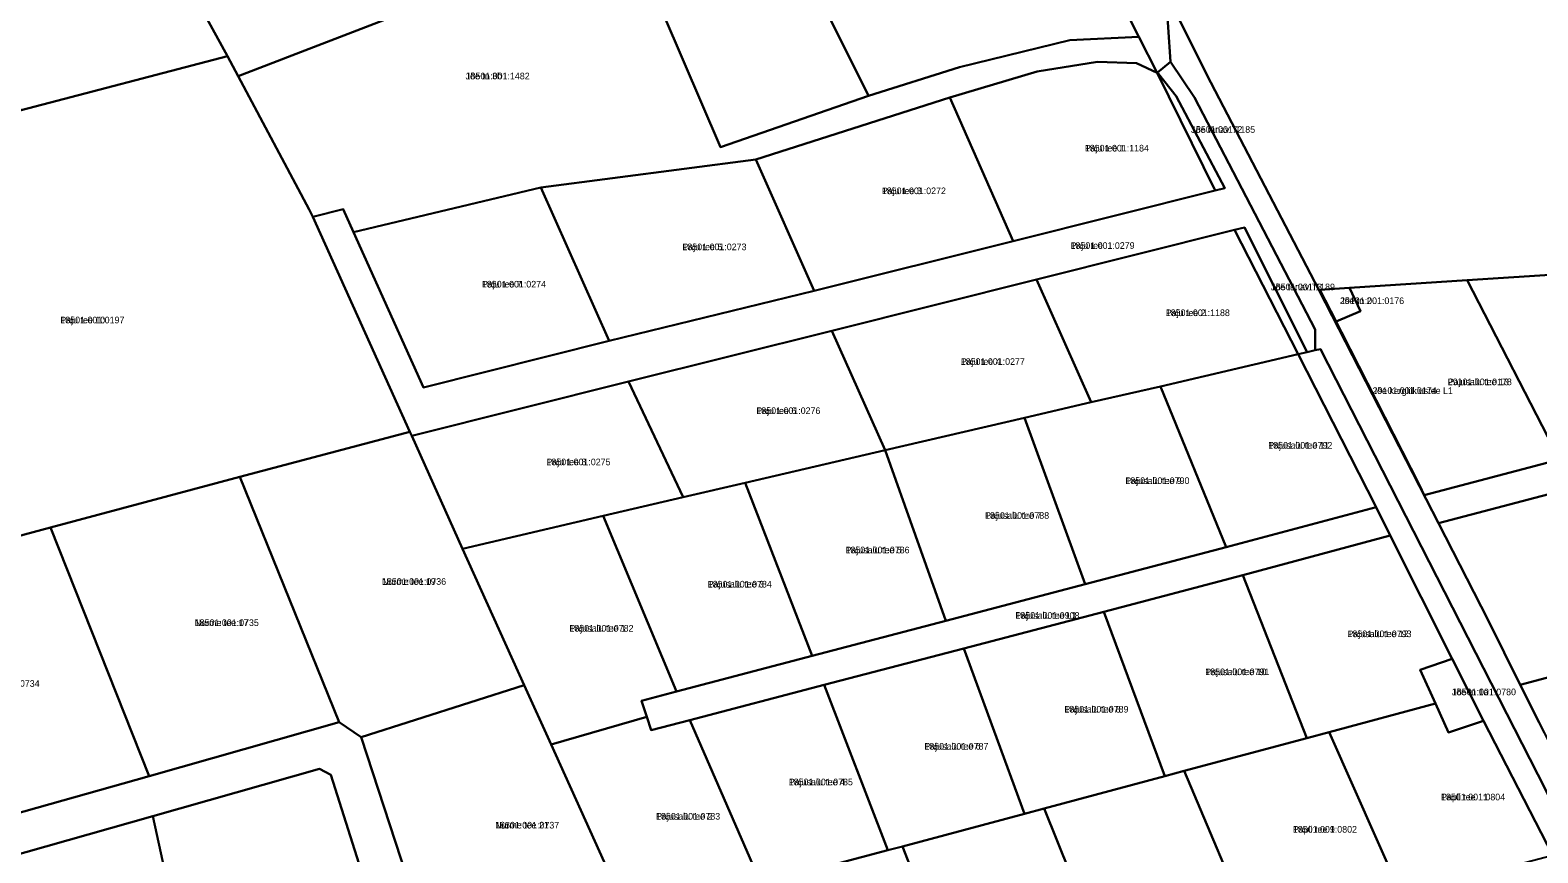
# Model space of a CAD drawing. Extents: x 660838 to 697091, y 6455678 to 6479886.
# Drawn here: x 663753.8 to 664095.1, y 6468415.5 to 6468601.6 of the extents above; entities that cross this region are included whole.
import ezdxf

# ---------------------------------------------------------------- set-up
doc = ezdxf.new("R2010")
doc.units = 0
for name, color, linetype in [('L_AADRESS', 7, 'Continuous'), ('PIIR', 7, 'Continuous'), ('TUNNUS', 7, 'Continuous')]:
    doc.layers.add(name, color=color, linetype=linetype)

msp = doc.modelspace()

# ---------------------------------------------------------------- linework, layer by layer
at = {"layer": 'PIIR'}
for points in [[(663826, 6468643.72), (663820.81, 6468654.22), (663828.99, 6468657.82), (663831.18, 6468658.79), (663832.32, 6468656.54), (663863.44, 6468668.53), (663896.27, 6468681.19), (663929.11, 6468693.85), (663953.19, 6468703.12), (663961.88, 6468706.49), (664010.85, 6468610.16), (664011.97, 6468594.44), (664008.93, 6468591.97), (664004.79, 6468600.1), (663975.18, 6468658.35), (663966.33, 6468675.78), (663956.97, 6468694.2), (663938.59, 6468687.11), (663900.86, 6468672.57), (663863.38, 6468658.13)], [(664156.44, 6468551.21), (664150.84, 6468549.63), (664113.09, 6468547.2), (664079.12, 6468545.02), (664052.46, 6468543.3), (664045.73, 6468542.87), (664045.52, 6468542.86), (664020.16, 6468591.48), (664010.85, 6468610.16), (664011.82, 6468610.76), (664029.43, 6468621.6), (664208.84, 6468678.98), (664257.87, 6468579.74), (664236.44, 6468573.71), (664197.17, 6468562.66)], [(663770.39, 6468646.95), (663815.27, 6468665.42), (663820.81, 6468654.22), (663826, 6468643.72), (663843.84, 6468607.7), (663800.86, 6468591.18), (663798.47, 6468595.74)], [(663918.76, 6468636.59), (663975.18, 6468658.35), (664004.79, 6468600.1), (663989.12, 6468599.37), (663964.17, 6468593.24), (663943.56, 6468586.75)], [(663713.8, 6468646.8), (663724.05, 6468628.36), (663767.34, 6468652.41), (663770.39, 6468646.95), (663798.47, 6468595.74), (663751.8, 6468583.46), (663734.19, 6468606.75), (663719.68, 6468625.93), (663709.43, 6468644.37)], [(663943.56, 6468586.75), (663910.1, 6468575.16), (663888.66, 6468625.04), (663918.76, 6468636.59)], [(663816.98, 6468561.02), (663800.86, 6468591.18), (663843.84, 6468607.7), (663881.29, 6468622.19), (663888.66, 6468625.04), (663910.1, 6468575.16), (663943.56, 6468586.75), (663964.17, 6468593.24), (663989.12, 6468599.37), (664004.79, 6468600.1), (664008.93, 6468591.97), (664004.24, 6468594.14), (663995.43, 6468594.42), (663981.79, 6468592.26), (663962.02, 6468586.4), (663918.09, 6468572.36), (663869.44, 6468565.97), (663827.01, 6468555.9), (663824.66, 6468561.08), (663817.81, 6468559.34)], [(664011.97, 6468594.44), (664010.85, 6468610.16), (664020.16, 6468591.48), (664045.52, 6468542.86), (664069.8, 6468495.5), (664072.61, 6468490.03), (664083.83, 6468468.15), (664091.12, 6468453.52), (664095.38, 6468444.97), (664120.83, 6468393.91), (664157.25, 6468320.55), (664198.71, 6468241.32), (664192.29, 6468241.62), (664146.38, 6468329.37), (664096.86, 6468429.82), (664045.92, 6468529.46), (664044.65, 6468529.2), (664044.72, 6468533.87), (664017.4, 6468586.35)], [(663798.47, 6468595.74), (663800.86, 6468591.18), (663816.98, 6468561.02), (663817.81, 6468559.34), (663839.73, 6468510.76), (663801.29, 6468500.55), (663758.39, 6468489.1), (663705.35, 6468474.8), (663686.09, 6468566.17), (663751.8, 6468583.46)], [(663840.19, 6468509.8), (663839.73, 6468510.76), (663817.81, 6468559.34), (663824.66, 6468561.08), (663827.01, 6468555.9), (663842.88, 6468520.78), (663884.88, 6468531.29), (663931.28, 6468542.6), (663976.3, 6468553.87), (664022.06, 6468565.31), (664024.26, 6468565.88), (664013.24, 6468586.67), (664009.19, 6468591.68), (664008.96, 6468591.94), (664008.93, 6468591.97), (664011.97, 6468594.44), (664017.4, 6468586.35), (664044.72, 6468533.87), (664044.65, 6468529.2), (664042.85, 6468528.78), (664028.71, 6468556.99), (664026.46, 6468556.4), (663981.59, 6468545.2), (663935.28, 6468533.6), (663889.24, 6468522.08)], [(663962.02, 6468586.4), (663981.79, 6468592.26), (663995.43, 6468594.42), (664004.24, 6468594.14), (664008.93, 6468591.97), (664022.06, 6468565.31), (663976.3, 6468553.87)], [(664008.93, 6468591.97), (664008.96, 6468591.94), (664009.19, 6468591.68), (664013.24, 6468586.67), (664024.26, 6468565.88), (664022.06, 6468565.31)], [(663918.09, 6468572.36), (663962.02, 6468586.4), (663976.3, 6468553.87), (663931.28, 6468542.6)], [(663869.44, 6468565.97), (663918.09, 6468572.36), (663931.28, 6468542.6), (663884.88, 6468531.29)], [(663827.01, 6468555.9), (663869.44, 6468565.97), (663884.88, 6468531.29), (663842.88, 6468520.78)], [(663981.59, 6468545.2), (664026.46, 6468556.4), (664040.86, 6468528.27), (664009.66, 6468521.02), (663994, 6468517.42)], [(664026.46, 6468556.4), (664028.71, 6468556.99), (664042.85, 6468528.78), (664040.86, 6468528.27)], [(664250.88, 6468545.67), (664254.62, 6468547.21), (664258.69, 6468545.53), (664259.7, 6468543.08), (664260.37, 6468541.46), (664258.69, 6468537.4), (664254.62, 6468535.71), (664251.28, 6468537.09), (664230.11, 6468531.51), (664198.4, 6468523.16), (664166.7, 6468514.82), (664134.99, 6468506.46), (664103.28, 6468498.11), (664072.61, 6468490.03), (664069.8, 6468495.5), (664069.85, 6468495.51), (664069.39, 6468496.43), (664100, 6468504.49), (664130.88, 6468512.62), (664170.96, 6468523.18), (664211.95, 6468533.97), (664249.71, 6468543.92), (664250.55, 6468545.53)], [(664079.12, 6468545.02), (664113.09, 6468547.2), (664130.88, 6468512.62), (664100, 6468504.49)], [(663935.28, 6468533.6), (663981.59, 6468545.2), (663994, 6468517.42), (663978.89, 6468513.87), (663947.33, 6468506.56)], [(664045.52, 6468542.86), (664045.73, 6468542.87), (664049.41, 6468535.71), (664050.65, 6468533.28), (664068.29, 6468498.63), (664069.39, 6468496.43), (664069.85, 6468495.51), (664069.8, 6468495.5)], [(664049.41, 6468535.71), (664045.73, 6468542.87), (664052.46, 6468543.3), (664054.92, 6468537.99)], [(664054.92, 6468537.99), (664052.46, 6468543.3), (664079.12, 6468545.02), (664100, 6468504.49), (664069.39, 6468496.43), (664068.29, 6468498.63), (664050.65, 6468533.28), (664049.41, 6468535.71)], [(663889.24, 6468522.08), (663935.28, 6468533.6), (663947.33, 6468506.56), (663915.64, 6468499.18), (663901.63, 6468495.92)], [(664061.69, 6468487.25), (664058.48, 6468493.66), (664040.86, 6468528.27), (664042.85, 6468528.78), (664044.65, 6468529.2), (664045.92, 6468529.46), (664096.86, 6468429.82), (664146.38, 6468329.37), (664192.29, 6468241.62), (664186.43, 6468241.89), (664182.99, 6468248.64), (664170.02, 6468274.46), (664156.03, 6468302.27), (664142.09, 6468329.5), (664138.93, 6468335.94), (664119.99, 6468372.84), (664101.86, 6468408.55), (664098.51, 6468414.91), (664082.82, 6468445.33), (664075.71, 6468459.37)], [(664009.66, 6468521.02), (664040.86, 6468528.27), (664058.48, 6468493.66), (664024.56, 6468484.63)], [(663840.19, 6468509.8), (663889.24, 6468522.08), (663901.63, 6468495.92), (663883.52, 6468491.7), (663851.66, 6468484.26)], [(663978.89, 6468513.87), (663994, 6468517.42), (664009.66, 6468521.02), (664024.56, 6468484.63), (663992.61, 6468476.25)], [(663947.33, 6468506.56), (663978.89, 6468513.87), (663992.61, 6468476.25), (663961.09, 6468467.96)], [(663801.29, 6468500.55), (663839.73, 6468510.76), (663840.19, 6468509.8), (663851.66, 6468484.26), (663865.64, 6468453.42), (663828.73, 6468441.62), (663823.76, 6468445.04)], [(663915.64, 6468499.17), (663947.33, 6468506.56), (663961.09, 6468467.96), (663930.85, 6468460.03)], [(663758.39, 6468489.1), (663801.29, 6468500.55), (663823.76, 6468445.04), (663780.76, 6468432.84)], [(663883.52, 6468491.71), (663901.63, 6468495.92), (663915.64, 6468499.17), (663930.85, 6468460.03), (663900.1, 6468451.96)], [(664072.61, 6468490.03), (664103.28, 6468498.11), (664122.04, 6468461.69), (664091.12, 6468453.52), (664083.83, 6468468.15)], [(663851.66, 6468484.26), (663883.52, 6468491.71), (663900.1, 6468451.96), (663892.19, 6468449.87), (663893.39, 6468446.27), (663871.75, 6468439.96), (663865.64, 6468453.42)], [(664058.48, 6468493.66), (664061.69, 6468487.25), (664028.28, 6468478.29), (663996.82, 6468470.03), (663965.15, 6468461.74), (663933.58, 6468453.47), (663903.11, 6468445.49), (663894.39, 6468443.22), (663893.39, 6468446.27), (663892.19, 6468449.87), (663900.1, 6468451.96), (663930.85, 6468460.03), (663961.09, 6468467.96), (663992.61, 6468476.25), (664024.56, 6468484.63)], [(663702.13, 6468470.18), (663705.35, 6468474.8), (663758.39, 6468489.1), (663780.76, 6468432.84), (663744.03, 6468422.46), (663737.12, 6468420.02), (663707.49, 6468468.92)], [(664028.28, 6468478.29), (664061.69, 6468487.25), (664075.71, 6468459.37), (664068.46, 6468456.91), (664071.93, 6468449.23), (664047.87, 6468442.82), (664042.8, 6468441.46)], [(663996.82, 6468470.03), (664028.28, 6468478.29), (664042.8, 6468441.46), (664015.04, 6468434.01), (664010.69, 6468432.82)], [(663965.15, 6468461.74), (663996.82, 6468470.03), (664010.69, 6468432.82), (663983.33, 6468425.52), (663978.87, 6468424.33)], [(663933.58, 6468453.47), (663965.15, 6468461.74), (663978.87, 6468424.33), (663951.27, 6468416.94), (663947.98, 6468416.06)], [(664091.12, 6468453.52), (664122.04, 6468461.69), (664140.45, 6468425.92), (664109.42, 6468417.78), (664108.26, 6468419.99), (664095.38, 6468444.97)], [(664068.46, 6468456.91), (664075.71, 6468459.37), (664082.82, 6468445.33), (664074.89, 6468442.69), (664071.93, 6468449.23)], [(663828.73, 6468441.62), (663865.64, 6468453.42), (663871.74, 6468439.96), (663889.41, 6468400.95), (663846.76, 6468386.49)], [(663903.11, 6468445.49), (663933.58, 6468453.47), (663947.98, 6468416.06), (663919.26, 6468408.5)], [(664047.87, 6468442.82), (664071.93, 6468449.23), (664074.89, 6468442.69), (664082.82, 6468445.33), (664098.51, 6468414.91), (664064.26, 6468405.93)], [(663885.65, 6468244.29), (663877.74, 6468245.51), (663878.61, 6468251.58), (663874.54, 6468264.74), (663861.17, 6468307.93), (663858.61, 6468310.23), (663816.6, 6468318.2), (663780.04, 6468325.13), (663771.57, 6468326.94), (663725.97, 6468336.81), (663698.3, 6468342.78), (663700.87, 6468347.01), (663721.55, 6468388.74), (663737.12, 6468420.02), (663744.03, 6468422.46), (663780.76, 6468432.84), (663823.76, 6468445.04), (663828.73, 6468441.62), (663846.76, 6468386.49), (663845.6, 6468386.09), (663842.06, 6468384.89)], [(663871.75, 6468439.96), (663893.39, 6468446.27), (663894.39, 6468443.22), (663903.11, 6468445.49), (663919.26, 6468408.5), (663889.41, 6468400.95)], [(664015.04, 6468434.01), (664042.8, 6468441.46), (664047.87, 6468442.82), (664064.26, 6468405.93), (664030.62, 6468397.11)], [(663854.89, 6468320.1), (663856.77, 6468322.23), (663839.06, 6468378.91), (663821.86, 6468433.12), (663819.34, 6468434.52), (663781.58, 6468423.81), (663747.74, 6468414.2), (663742.48, 6468410.94), (663733.1, 6468391.92), (663713.01, 6468351.64), (663714.75, 6468348.46), (663781.7, 6468333.97)], [(663781.58, 6468423.81), (663819.34, 6468434.52), (663821.86, 6468433.12), (663839.06, 6468378.91), (663792.61, 6468373.3)], [(663983.33, 6468425.52), (664010.69, 6468432.82), (664015.04, 6468434.01), (664030.62, 6468397.11), (663998.2, 6468388.6)], [(663733.1, 6468391.92), (663742.48, 6468410.94), (663747.74, 6468414.2), (663781.58, 6468423.81), (663792.61, 6468373.3)], [(663951.27, 6468416.94), (663978.87, 6468424.33), (663983.33, 6468425.52), (663998.2, 6468388.6), (663965.71, 6468380.05)], [(663919.26, 6468408.5), (663947.98, 6468416.06), (663951.27, 6468416.94), (663965.71, 6468380.05), (663935.15, 6468372.06)]]:
    msp.add_lwpolyline(points, close=True, dxfattribs=at)

# ---------------------------------------------------------------- texts
at = {"layer": 'L_AADRESS'}
for s, p in [('Jõe tn 3b', (663852.38, 6468590.47)), ('Jõe tänav T2', (664016.59, 6468578.37)), ('Paju tee 1', (663992.55, 6468574.15)), ('Paju tee 3', (663946.6, 6468564.5)), ('Paju tee 5', (663901.46, 6468551.82)), ('Paju tee', (663989.31, 6468552.12)), ('Paju tee 7', (663856.08, 6468543.38)), ('Jõe tänav T3', (664034.66, 6468542.76)), ('Jõe tn 2', (664050.32, 6468539.63)), ('Paju tee 10', (663760.64, 6468535.27)), ('Paju tee 2', (664010.87, 6468536.91)), ('Paju tee 4', (663964.47, 6468525.88)), ('Pajusalu tee 13', (664074.7, 6468521.28)), ('Jõe kergliiklustee L1', (664057.69, 6468519.3)), ('Paju tee 6', (663918.19, 6468514.76)), ('Pajusalu tee 11', (664034.07, 6468506.93)), ('Paju tee 8', (663870.68, 6468503.17)), ('Pajusalu tee 9', (664001.73, 6468498.92)), ('Pajusalu tee 7', (663969.97, 6468491.05)), ('Pajusalu tee 5', (663938.37, 6468483.24)), ('Nurme tee 19', (663833.46, 6468476.11)), ('Pajusalu tee 3', (663907.19, 6468475.51)), ('Nurme tee 17', (663791.07, 6468466.8)), ('Pajusalu tee L1', (663976.83, 6468468.44)), ('Pajusalu tee 1', (663875.88, 6468465.54)), ('Pajusalu tee 12', (664052, 6468464.28)), ('Pajusalu tee 10', (664019.81, 6468455.68)), ('Jõe tn 1a', (664075.64, 6468451.14)), ('Pajusalu tee 8', (663987.92, 6468447.22)), ('Pajusalu tee 6', (663956.22, 6468438.83)), ('Pajusalu tee 4', (663925.54, 6468430.76)), ('Papli tee 11', (664073.19, 6468427.36)), ('Pajusalu tee 2', (663895.5, 6468423)), ('Nurme tee 21', (663859.07, 6468420.99)), ('Papli tee 9', (664039.65, 6468420.05))]:
    msp.add_text(s, height=1.5, dxfattribs=at).set_placement(p)
at = {"layer": 'TUNNUS'}
for s, p in [('18501:001:1482', (663852.38, 6468590.47)), ('18501:001:1185', (664016.59, 6468578.37)), ('18501:001:1184', (663992.55, 6468574.15)), ('18501:001:0272', (663946.6, 6468564.5)), ('18501:001:0273', (663901.46, 6468551.82)), ('18501:001:0279', (663989.31, 6468552.12)), ('18501:001:0274', (663856.08, 6468543.38)), ('18501:001:1189', (664034.66, 6468542.76)), ('29101:001:0176', (664050.32, 6468539.63)), ('18501:001:0197', (663760.64, 6468535.27)), ('18501:001:1188', (664010.87, 6468536.91)), ('18501:001:0277', (663964.47, 6468525.88)), ('29101:001:0178', (664074.7, 6468521.28)), ('29101:001:0174', (664057.69, 6468519.3)), ('18501:001:0276', (663918.19, 6468514.76)), ('18501:001:0792', (664034.07, 6468506.93)), ('18501:001:0275', (663870.68, 6468503.17)), ('18501:001:0790', (664001.73, 6468498.92)), ('18501:001:0788', (663969.97, 6468491.05)), ('18501:001:0786', (663938.37, 6468483.24)), ('18501:001:0736', (663833.46, 6468476.11)), ('18501:001:0784', (663907.19, 6468475.51)), ('18501:001:0735', (663791.07, 6468466.8)), ('18501:001:0908', (663976.83, 6468468.44)), ('18501:001:0782', (663875.88, 6468465.54)), ('18501:001:0793', (664052, 6468464.28)), ('18501:001:0734', (663741.45, 6468453.04)), ('18501:001:0791', (664019.81, 6468455.68)), ('18501:001:0780', (664075.64, 6468451.14)), ('18501:001:0789', (663987.92, 6468447.22)), ('18501:001:0787', (663956.22, 6468438.83)), ('18501:001:0785', (663925.54, 6468430.76)), ('18501:001:0804', (664073.19, 6468427.36)), ('18501:001:0783', (663895.5, 6468423)), ('18501:001:0737', (663859.07, 6468420.99)), ('18501:001:0802', (664039.65, 6468420.05))]:
    msp.add_text(s, height=1.5, dxfattribs=at).set_placement(p)

doc.saveas('drawing.dxf')
